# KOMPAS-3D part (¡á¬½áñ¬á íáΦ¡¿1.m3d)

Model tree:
1. Эскиз:1
2. Операция выдавливания:1
     Расстояние 1 = 40
3. Эскиз:7
4. Вырезать элемент выдавливания:6
     Расстояние 2 = 0.165976; Расстояние 1 = 2; Угол 1 = 71
5. Эскиз:8
6. Вырезать элемент выдавливания:7
     Расстояние 2 = 73.9614; Угол 2 = 1; Расстояние 1 = 71.8317; Угол 1 = 1

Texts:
  накладка башни1
  stalker61
  Сплав АЛ8  ГОСТ 1583-93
